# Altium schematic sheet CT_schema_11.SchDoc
size 386 x 278 mm
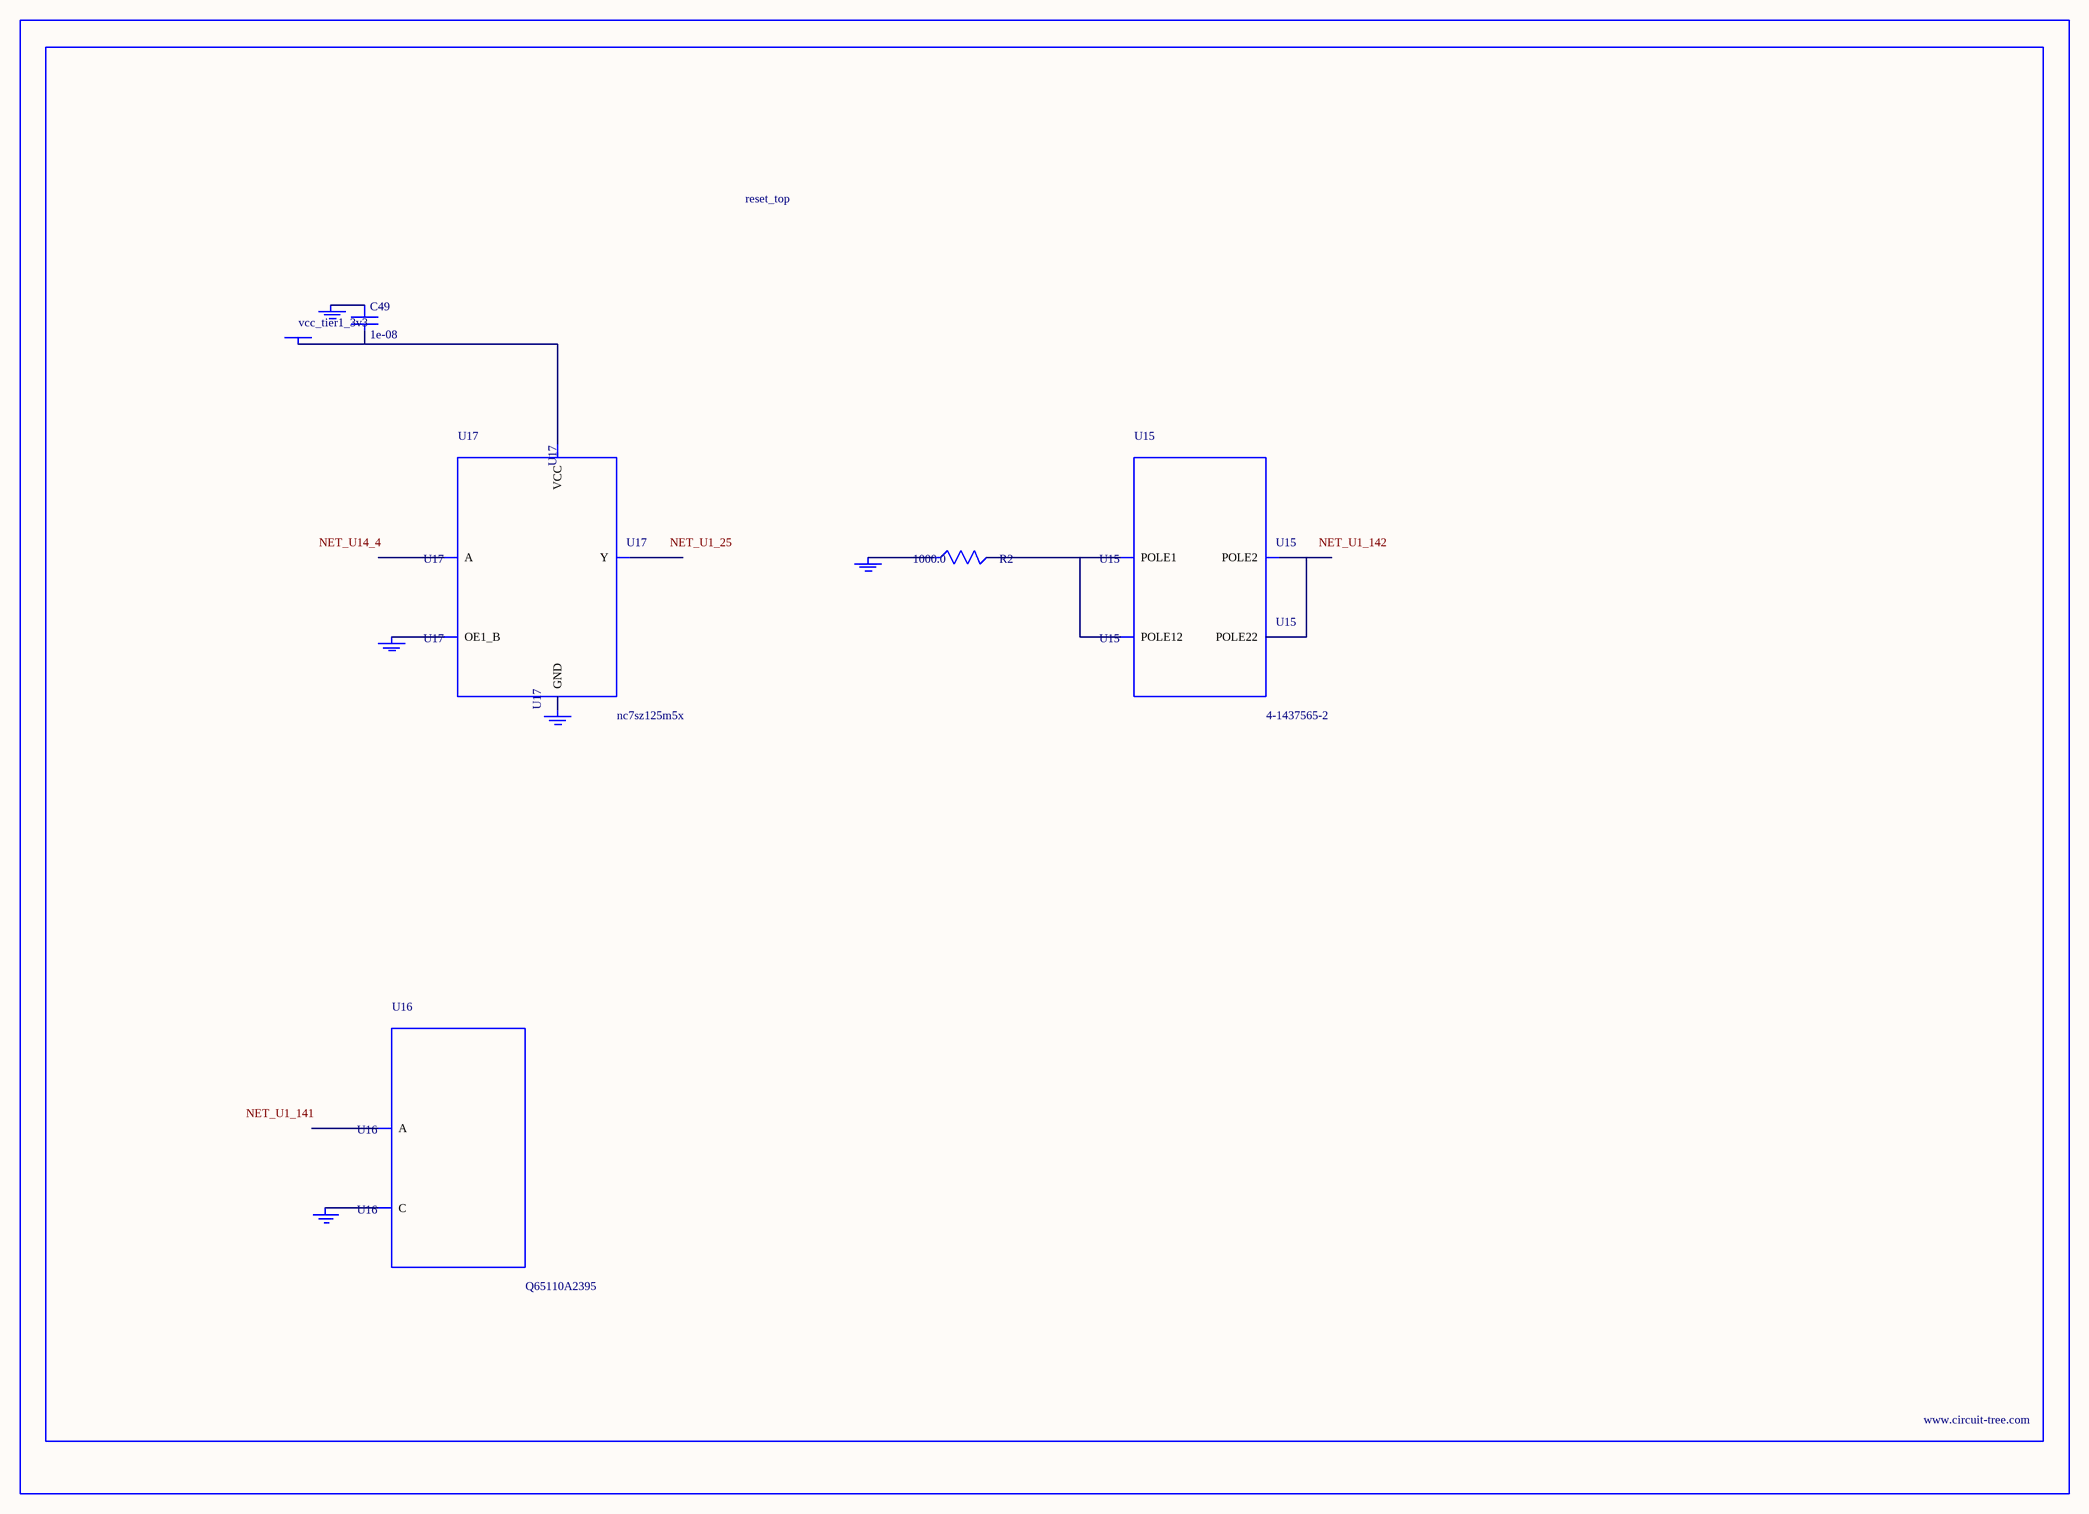
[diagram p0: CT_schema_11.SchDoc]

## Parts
BORDER10  (no value)
C49  1e-08  [C0402]
GND_INSTANCE_10_0  (no value)
GND_INSTANCE_10_1  (no value)
GND_INSTANCE_10_2  (no value)
GND_INSTANCE_10_3  (no value)
GND_INSTANCE_10_4  (no value)
POWER_INSTANCE_10_0  vcc_tier1_3v3
R2  1000.0  [R0603]
U15  4-1437565-2  [SW_4-1437565-2]
U16  Q65110A2395  [LGM67K-G1J2-24-Z]
U17  nc7sz125m5x  [NC7SZ125M5X]

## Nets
NetC49_1: C49.1 GND_INSTANCE_10_2.0(GND)
NetC49_2: C49.2 POWER_INSTANCE_10_0.0(PWR) U17.5(VCC)
NetGND_INSTANCE_10_0_0: GND_INSTANCE_10_0.0(GND) R2.1
NetGND_INSTANCE_10_1_0: GND_INSTANCE_10_1.0(GND) U16.C
NetGND_INSTANCE_10_3_0: GND_INSTANCE_10_3.0(GND) U17.1(OE1_B)
NetGND_INSTANCE_10_4_0: GND_INSTANCE_10_4.0(GND) U17.3(GND)
NetR2_2: R2.2 U15.1(POLE1) U15.2(POLE12)
NetU15_3: U15.3(POLE2) U15.4(POLE22)

Not connected (* = marked no-connect by the designer): U16 A; U17 2(A) 4(Y)

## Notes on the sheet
- Labels drawn without touching a wire or pin: NET_U1_25, NET_U1_141, NET_U1_142, NET_U14_4

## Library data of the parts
BORDER10 = BORDER_PAGE10
C49 = C0402C103K3RAC
GND_INSTANCE_10_0-GND_INSTANCE_10_4 = GND
POWER_INSTANCE_10_0 = PWR
R2 = RC0603JR-071KL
